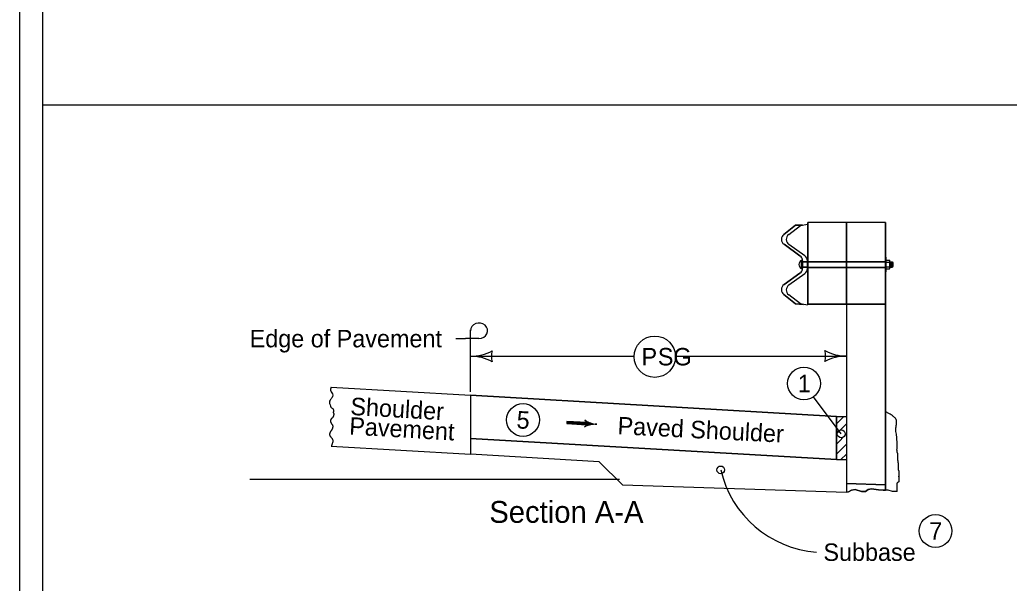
# Model space of a CAD drawing. Extents: x 6410 to 81668, y 3928 to 11667.
# Drawn here: x 10133 to 11038, y 8912 to 9428 of the extents above; entities that cross this region are included whole.
import ezdxf

# ---------------------------------------------------------------- set-up
doc = ezdxf.new("R2010")
doc.units = 0
for name, color, linetype in [('dsnCellElements', 7, 'Continuous'), ('dsnNonPlotable', 7, 'Continuous'), ('dsnShtPlotShapeBatchPrint', 7, 'Continuous'), ('dsnStdBlockModified', 7, 'Continuous'), ('Level 11', 7, 'Continuous'), ('Level 14', 7, 'Continuous'), ('Level 3', 7, 'Continuous'), ('Level 7', 7, 'Continuous'), ('Level 8', 7, 'Continuous')]:
    doc.layers.add(name, color=color, linetype=linetype)

msp = doc.modelspace()

# ---------------------------------------------------------------- linework, layer by layer
at = {"layer": 'dsnCellElements'}
for p, q in [((10545.11, 9123.38), (10545.11, 9144.24)), ((10531.74, 9136.23), (10540.43, 9136.23)), ((10552.92, 9136.23), (10540.43, 9136.23)), ((10545.11, 9087.45), (10545.11, 9123.38)), ((10651.5, 9058.34), (10633.29, 9059.39)), ((10651.51, 9059.35), (10651.51, 9059.35)), ((10651.39, 9057.4), (10651.39, 9057.4))]:
    msp.add_line(p, q, dxfattribs=at)
for points in [[(10651.52, 9059.29), (10633.36, 9060.33), (10633.23, 9058.45), (10651.39, 9057.4), (10651.45, 9059.02), (10633.58, 9060.11), (10633.52, 9058.61), (10651.01, 9057.67), (10651.13, 9058.79), (10633.81, 9059.85), (10633.79, 9058.85), (10650.8, 9057.87), (10650.89, 9058.57), (10634, 9059.63), (10633.98, 9059.07), (10650.59, 9058.13)], [(10651.12, 9060.54), (10651.81, 9059.37), (10651.79, 9057.73), (10651.03, 9056.33), (10653.79, 9057.19), (10656.98, 9057.84), (10657.88, 9057.98), (10655.64, 9058.53), (10652.41, 9059.76), (10651.47, 9060.29), (10651.59, 9056.78), (10656.54, 9057.99), (10651.9, 9059.58), (10651.91, 9057.16), (10655.31, 9058.09), (10652.31, 9058.95), (10652.08, 9057.56), (10654.24, 9058.06), (10652.65, 9058.57), (10652.51, 9057.91), (10653.3, 9058.08)]]:
    msp.add_lwpolyline(points, dxfattribs=at)
for centre, major_axis, start_param, end_param in [((10552.92, 9143.37), (-7.81, 0), 1.570796, 6.283185), ((10647.73, 9058.56), (3.88, 0), 5.202895, 7.237436), ((10662.79, 9077.98), (-22.17, 0), 0.954258, 1.478381), ((10660, 9037.56), (22.17, 0), 1.537172, 2.061295)]:
    msp.add_ellipse(centre, major_axis=major_axis, ratio=0.913811, start_param=start_param, end_param=end_param, dxfattribs=at)
at = {"layer": 'dsnNonPlotable'}
msp.add_line((10153.18, 9917.9), (10153.18, 8307.9), dxfattribs=at)
at = {"layer": 'dsnShtPlotShapeBatchPrint'}
for p, q in [((10545.11, 9120.06), (10694.94, 9120.06)), ((10732.8, 9120.22), (10889.5, 9120.22))]:
    msp.add_line(p, q, dxfattribs=at)
msp.add_circle((10713.87, 9119.66), 18.93, dxfattribs=at)
for centre, radius, start, end in [((10545.11, 9162.56), 42.5, 270, 298.07249), ((10580.75, 9120.06), 16.42, 162.26665, 197.73335), ((10853.87, 9120.22), 16.42, 342.26665, 17.73335), ((10889.5, 9162.72), 42.5, 241.92751, 270), ((10545.11, 9077.56), 42.5, 61.92751, 90), ((10889.5, 9077.72), 42.5, 90, 118.07249), ((10869.48, 9038.15), 97.76, 193.07698, 265.55799)]:
    msp.add_arc(centre, radius, start, end, dxfattribs=at)
at = {"layer": 'dsnStdBlockModified'}
for p, q in [((10832.02, 9231.67), (10842.78, 9240.07)), ((10836.45, 9231.44), (10847.23, 9239.85)), ((10842.78, 9240.07), (10849.11, 9240.18)), ((10847.23, 9239.85), (10853.56, 9240.97)), ((10925.05, 9242.43), (10853.96, 9242.43)), ((10853.96, 9167.78), (10853.96, 9242.43)), ((10889.5, 9167.78), (10889.5, 9242.43)), ((10925.05, 9242.43), (10925.05, 8997.39)), ((10846.72, 9212.14), (10832.21, 9222.55)), ((10851.19, 9211.9), (10836.63, 9222.35)), ((10848.34, 9200.03), (10848.34, 9208.11)), ((10848.34, 9206.42), (10853.77, 9206.42)), ((10849.12, 9200.69), (10849.11, 9207.5)), ((10849.11, 9200.69), (10849.12, 9204.1)), ((10849.12, 9204.1), (10849.12, 9200.69)), ((10849.29, 9206.42), (10853.96, 9206.42)), ((10853.56, 9203.88), (10853.56, 9207.29)), ((10853.56, 9200.47), (10853.56, 9203.88)), ((10853.56, 9203.88), (10853.56, 9200.47)), ((10853.96, 9206.76), (10925.05, 9206.76)), ((10853.96, 9206.42), (10925.05, 9206.42)), ((10925.05, 9210.73), (10925.73, 9210.73)), ((10925.73, 9197.4), (10925.73, 9210.73)), ((10925.73, 9208.1), (10928.7, 9208.1)), ((10925.73, 9206.08), (10928.7, 9206.08)), ((10929.06, 9201.03), (10929.06, 9207.09)), ((10929.06, 9206.39), (10931.43, 9206.39)), ((10929.95, 9206.39), (10929.95, 9201.73)), ((10930.69, 9206.39), (10930.69, 9201.73)), ((10931.43, 9206.39), (10931.88, 9205.86)), ((10931.43, 9206.39), (10931.43, 9201.73)), ((10931.88, 9205.86), (10931.88, 9202.26)), ((10832.21, 9185.65), (10846.72, 9196.06)), ((10836.63, 9185.41), (10851.19, 9195.86)), ((10848.34, 9201.76), (10853.96, 9201.76)), ((10853.95, 9201.42), (10925.05, 9201.42)), ((10853.96, 9201.76), (10925.05, 9201.76)), ((10925.05, 9197.4), (10925.73, 9197.4)), ((10925.73, 9202.04), (10928.7, 9202.04)), ((10925.73, 9200.02), (10928.7, 9200.02)), ((10929.06, 9201.73), (10931.43, 9201.73)), ((10931.88, 9202.26), (10931.43, 9201.73)), ((10842.78, 9168.13), (10832.02, 9176.52)), ((10847.23, 9167.91), (10836.45, 9176.32)), ((10849.88, 9167.44), (10842.78, 9168.13)), ((10853.56, 9166.79), (10847.23, 9167.91)), ((10889.5, 9167.78), (10853.96, 9167.78)), ((10889.5, 9167.78), (10889.5, 8995.55)), ((10417.65, 9091.72), (10545.11, 9084.31)), ((10545.11, 9084.31), (10545.11, 9030.29)), ((10545.11, 9084.31), (10880.25, 9064.82)), ((10880.25, 9064.82), (10545.11, 9084.31)), ((10545.11, 9084.31), (10545.11, 9044.71)), ((10880.25, 9058.07), (10886.99, 9064.82)), ((10880.25, 9058.07), (10886.99, 9064.82)), ((10880.25, 9058.07), (10886.99, 9064.82)), ((10880.25, 9058.07), (10886.99, 9064.82)), ((10880.25, 9064.82), (10889.49, 9064.82)), ((10880.25, 9064.82), (10880.25, 9025.39)), ((10880.25, 9025.39), (10880.25, 9064.82)), ((10880.25, 9048.89), (10889.49, 9058.12)), ((10880.25, 9048.89), (10889.49, 9058.12)), ((10880.25, 9048.89), (10889.49, 9058.12)), ((10880.25, 9048.89), (10889.49, 9058.12)), ((10935.1, 9058.05), (10935.1, 9058.05)), ((10880.25, 9025.39), (10545.11, 9044.71)), ((10545.11, 9044.71), (10880.25, 9025.39)), ((10880.25, 9039.66), (10889.49, 9048.9)), ((10880.25, 9039.66), (10889.49, 9048.9)), ((10880.25, 9039.66), (10889.49, 9048.9)), ((10880.25, 9039.66), (10889.49, 9048.9)), ((10417.68, 9037.7), (10545.11, 9030.29)), ((10880.25, 9030.43), (10889.49, 9039.67)), ((10662.95, 9023.5), (10545.11, 9030.29)), ((10662.95, 9023.5), (10684.29, 9002.28)), ((10880.25, 9025.39), (10889.49, 9025.39)), ((10884.35, 9025.39), (10889.49, 9030.53)), ((10343.06, 9007.46), (10681.56, 9007.46)), ((10684.29, 9002.28), (10889.5, 8995.55))]:
    msp.add_line(p, q, dxfattribs=at)
for points in [[(10929.05, 9201.36), (10929, 9201.62), (10928.96, 9201.8), (10928.87, 9201.95), (10928.75, 9202.04), (10928.83, 9202.14), (10928.91, 9202.36), (10928.97, 9202.68), (10929.05, 9203.43), (10929.05, 9201.35), (10929.03, 9201.49), (10928.99, 9201.71), (10928.91, 9201.92), (10928.79, 9202.03), (10928.83, 9202.12), (10928.89, 9202.27), (10928.99, 9202.77), (10929.03, 9203.15), (10929.03, 9201.54), (10929, 9201.66), (10928.96, 9201.83), (10928.83, 9202.03), (10928.88, 9202.2), (10928.96, 9202.54), (10929.02, 9202.86), (10929.01, 9201.7), (10928.97, 9201.83), (10928.86, 9202.02), (10928.9, 9202.24), (10928.96, 9202.5), (10928.99, 9202.67), (10928.99, 9201.8), (10928.93, 9201.91), (10928.88, 9202.03), (10928.97, 9202.48), (10928.97, 9201.88), (10928.9, 9202.02), (10928.95, 9202.31), (10928.95, 9201.96), (10928.92, 9202.03), (10928.93, 9202.13), (10928.93, 9202.06)], [(10928.76, 9206.09), (10928.83, 9206.13), (10928.91, 9206.23), (10928.99, 9206.45), (10929.05, 9206.74), (10929.05, 9204.79), (10928.99, 9205.3), (10928.94, 9205.67), (10928.82, 9206), (10928.76, 9206.08), (10928.82, 9206.09), (10928.92, 9206.24), (10929.01, 9206.46), (10929.03, 9206.62), (10929.03, 9205.08), (10928.96, 9205.57), (10928.9, 9205.84), (10928.8, 9206.06), (10928.83, 9206.07), (10928.97, 9206.29), (10929.01, 9206.44), (10929.01, 9205.34), (10928.82, 9206.05), (10928.99, 9206.33), (10928.99, 9205.48), (10928.85, 9206.04), (10928.97, 9206.26), (10928.98, 9205.62), (10928.87, 9206.02), (10928.96, 9206.2), (10928.96, 9205.78), (10928.89, 9206.01), (10928.94, 9206.12), (10928.94, 9205.92), (10928.91, 9205.99), (10928.92, 9206.04)], [(10935.57, 9034.21), (10935.51, 9033.94), (10935.51, 9033.74), (10935.51, 9033.55), (10935.51, 9033.35), (10935.51, 9033.15), (10935.51, 9032.96), (10935.51, 9032.67), (10935.51, 9032.47), (10935.61, 9032.18), (10935.71, 9031.88), (10935.9, 9031.69), (10935.9, 9031.49), (10936, 9031.3), (10936, 9031.1), (10936, 9030.91), (10936.1, 9030.81), (10936.1, 9030.61), (10936.1, 9030.42), (10936.1, 9030.22), (10936.1, 9030.03), (10936.1, 9029.83), (10936.1, 9029.54), (10936.1, 9029.25), (10936.1, 9029.05), (10936.1, 9028.76), (10936.1, 9028.56), (10936.1, 9028.37), (10936.2, 9028.27), (10936.2, 9028.07), (10936.2, 9027.88), (10936.2, 9027.68), (10936.2, 9027.49), (10936.2, 9027.29), (10936.2, 9027.1), (10936.2, 9026.9), (10936.2, 9026.71), (10936.2, 9026.51), (10936.2, 9026.32), (10936.2, 9026.12), (10936.2, 9025.92), (10936.2, 9025.73), (10936.2, 9025.53), (10936.2, 9025.34), (10936.2, 9025.14), (10936.2, 9024.95), (10936.2, 9024.75), (10936.29, 9024.65), (10936.29, 9024.46), (10936.29, 9024.26), (10936.39, 9024.17), (10936.39, 9023.97), (10936.39, 9023.77), (10936.49, 9023.68), (10936.49, 9023.48), (10936.49, 9023.29), (10936.49, 9023.09), (10936.49, 9022.8), (10936.59, 9022.5), (10936.59, 9022.31), (10936.59, 9022.11), (10936.59, 9021.92), (10936.59, 9021.72), (10936.59, 9021.53), (10936.59, 9021.33), (10936.59, 9021.14), (10936.59, 9020.94), (10936.59, 9020.75), (10936.59, 9020.55), (10936.59, 9020.36), (10936.59, 9020.16), (10936.59, 9019.96), (10936.59, 9019.77), (10936.59, 9019.57), (10936.59, 9019.38), (10936.59, 9019.18), (10936.59, 9018.99), (10936.59, 9018.79), (10936.59, 9018.6), (10936.59, 9018.4), (10936.59, 9018.21), (10936.59, 9018.01), (10936.59, 9017.81), (10936.59, 9017.62), (10936.59, 9017.42), (10936.59, 9017.23), (10936.59, 9017.03), (10936.59, 9016.84), (10936.68, 9016.74), (10936.68, 9016.45), (10936.68, 9016.25), (10936.78, 9016.06), (10936.88, 9015.76), (10936.88, 9015.57), (10936.98, 9015.47), (10936.98, 9015.27), (10937.07, 9015.18), (10937.17, 9015.08), (10937.17, 9014.88), (10937.17, 9014.69), (10937.17, 9014.49), (10937.27, 9014.4), (10937.27, 9014.2), (10937.27, 9014), (10937.27, 9013.81), (10937.27, 9013.61), (10937.27, 9013.42), (10937.27, 9013.22), (10937.27, 9013.03), (10937.27, 9012.83), (10937.27, 9012.64), (10937.27, 9012.44), (10937.27, 9012.25), (10937.27, 9012.05), (10937.27, 9011.85), (10937.27, 9011.66), (10937.27, 9011.46), (10937.27, 9011.27), (10937.27, 9011.07), (10937.27, 9010.88), (10937.27, 9010.68), (10937.27, 9010.49), (10937.27, 9010.29), (10937.27, 9010.1), (10937.27, 9009.9), (10937.27, 9009.71), (10937.27, 9009.51), (10937.27, 9009.51), (10937.27, 9009.8), (10937.27, 9010), (10937.27, 9010.19), (10937.27, 9010), (10937.27, 9009.8), (10937.27, 9009.61), (10937.27, 9009.41), (10937.27, 9009.22), (10937.27, 9009.02), (10937.27, 9008.83), (10937.27, 9008.63), (10937.27, 9008.44), (10937.27, 9008.24), (10937.27, 9008.04), (10937.27, 9007.85), (10937.27, 9007.65), (10937.27, 9007.46), (10937.27, 9007.26), (10937.17, 9007.16), (10937.17, 9006.97), (10937.17, 9006.77), (10937.17, 9006.58), (10937.17, 9006.38), (10937.17, 9006.19), (10937.17, 9005.99), (10937.17, 9005.8), (10937.17, 9005.6), (10937.17, 9005.41), (10937.17, 9005.21), (10937.07, 9005.11), (10936.98, 9004.92), (10936.88, 9004.82), (10936.78, 9004.72), (10936.68, 9004.62), (10936.49, 9004.53), (10936.29, 9004.53), (10936.2, 9004.43), (10936.1, 9004.33), (10936, 9004.23), (10935.8, 9004.14), (10935.71, 9004.04), (10935.71, 9003.84), (10935.61, 9003.75), (10935.61, 9003.55), (10935.61, 9003.35), (10935.61, 9003.16), (10935.61, 8996.34)], [(10935.74, 8996.34), (10931.59, 8996.22), (10927.46, 8997.39), (10922.9, 8997.39), (10918.66, 8997.81), (10912.41, 8998.56), (10909.33, 8997.92), (10906.68, 8996.12), (10902.97, 8996.33), (10897.36, 8997.92), (10894.07, 8997.39), (10891.31, 8995.8), (10889.5, 8995.55)]]:
    msp.add_lwpolyline(points, dxfattribs=at)
msp.add_circle((10593.23, 9061.73), 15, dxfattribs=at)
for centre, radius, start, end in [((10835.49, 9227.18), 5.68, 127.75002, 234.69086), ((10839.94, 9226.96), 5.68, 127.75002, 234.69086), ((10850.42, 9204.08), 4.54, 117.20289, 242.8461), ((10843.44, 9207.5), 5.68, 360, 54.69099), ((10847.88, 9207.28), 5.68, 360, 54.69099), ((10843.44, 9200.69), 5.68, 305.30901, 0), ((10847.88, 9200.47), 5.68, 305.30901, 0), ((10835.49, 9181.01), 5.68, 125.30914, 232.24998), ((10839.94, 9180.79), 5.68, 125.30914, 232.24998)]:
    msp.add_arc(centre, radius, start, end, dxfattribs=at)
for centre in [(10928.7, 9207.09), (10928.7, 9201.03)]:
    msp.add_ellipse(centre, major_axis=(0, -1.01), ratio=0.362258, start_param=6.283156, end_param=9.424748, dxfattribs=at)
for points in [[(10417.65, 9091.72), (10417.15, 9088.11), (10418.19, 9086.61), (10419.05, 9084.31), (10418.45, 9082.25), (10416.54, 9079.88), (10416.02, 9077.98), (10416.54, 9075.68), (10417.41, 9073.3), (10418.45, 9072.59), (10419.83, 9070.06), (10419.82, 9069.22)], [(10417.86, 9052.11), (10418.07, 9052.35), (10418.27, 9052.61), (10418.62, 9053.17), (10418.9, 9053.76), (10419.02, 9054.07), (10419.12, 9054.39), (10419.25, 9055.01), (10419.3, 9055.63), (10419.25, 9056.21), (10419.19, 9056.49), (10419.16, 9056.63), (10419.11, 9056.76), (10418.9, 9057.13), (10418.62, 9057.49), (10418.32, 9057.86), (10418.07, 9058.26), (10417.93, 9058.54), (10417.79, 9058.83), (10417.53, 9059.4), (10417.33, 9059.97), (10417.26, 9060.26), (10417.2, 9060.56), (10417.19, 9060.68), (10417.19, 9060.81), (10417.34, 9061.59), (10417.55, 9062.11), (10417.81, 9062.62), (10418.25, 9063.25), (10418.77, 9063.8), (10419.29, 9064.35), (10419.52, 9064.65), (10419.72, 9064.99), (10419.92, 9065.46), (10420.08, 9065.94), (10420.18, 9066.42), (10420.22, 9066.65), (10420.23, 9066.77), (10420.24, 9066.89), (10420.19, 9067.4), (10420.04, 9067.92), (10419.99, 9068.04), (10419.93, 9068.17), (10419.88, 9068.3), (10419.86, 9068.43), (10419.82, 9069.22)], [(10935.57, 9034.21), (10935.89, 9037.11), (10935.67, 9041.98), (10935.23, 9047.73), (10934.56, 9052.15), (10934.78, 9055.47), (10935.23, 9059.67), (10934.56, 9062.76), (10932.35, 9064.75), (10930.36, 9066.52), (10928.15, 9067.63), (10925.94, 9068.96), (10925.06, 9069.62)], [(10417.86, 9052.11), (10417.64, 9051.87), (10417.4, 9051.64), (10417.16, 9051.39), (10416.98, 9051.13), (10416.84, 9050.84), (10416.7, 9050.56), (10416.44, 9049.98), (10416.33, 9049.7), (10416.23, 9049.41), (10416.16, 9049.12), (10416.13, 9048.98), (10416.11, 9048.83), (10416.12, 9048.31), (10416.25, 9047.8), (10416.46, 9047.28), (10416.72, 9046.77), (10417.16, 9046.13), (10417.68, 9045.59), (10418.2, 9045.04), (10418.43, 9044.73), (10418.63, 9044.39), (10419.03, 9043.45), (10419.14, 9042.97), (10419.15, 9042.49), (10419.11, 9042.2), (10419.06, 9041.92), (10419.01, 9041.63), (10418.94, 9041.35), (10418.63, 9040.2), (10418.45, 9039.59), (10418.25, 9038.99), (10418.03, 9038.4), (10417.9, 9038.11), (10417.76, 9037.82), (10417.68, 9037.7)]]:
    msp.add_spline(points, degree=3, dxfattribs=at)
at = {"layer": 'Level 11'}
for p, q in [((12308.76, 9349.9), (10153.18, 9349.9)), ((10884.57, 9048.99), (10859.18, 9082.92))]:
    msp.add_line(p, q, dxfattribs=at)
at = {"layer": 'Level 14'}
msp.add_circle((10774.25, 9016.03), 3.54, dxfattribs=at)
at = {"layer": 'Level 3'}
for p, q in [((10832.21, 9222.55), (10846.72, 9212.14)), ((10846.72, 9196.06), (10832.21, 9185.65))]:
    msp.add_line(p, q, dxfattribs=at)
for points in [[(10836.46, 9231.45), (10836.45, 9231.44), (10847.23, 9239.85), (10849.11, 9240.18), (10842.78, 9240.07), (10832.02, 9231.67)], [(10889.5, 9206.76), (10889.5, 9242.43), (10853.96, 9242.43), (10853.96, 9206.76), (10853.96, 9206.76), (10889.5, 9206.76)], [(10925.05, 9206.76), (10925.05, 9210.76), (10925.05, 9242.43), (10889.5, 9242.43), (10889.5, 9206.76), (10925.05, 9206.76)], [(10851.17, 9211.92), (10851.19, 9211.9), (10836.63, 9222.35), (10836.66, 9222.33)], [(10849.11, 9207.5), (10849.11, 9206.42), (10853.56, 9206.42), (10853.56, 9207.29), (10853.56, 9207.28)], [(10853.96, 9206.42), (10853.96, 9201.76), (10853.96, 9201.76), (10889.5, 9201.76), (10889.5, 9206.42), (10853.96, 9206.42), (10853.96, 9206.42)], [(10925.05, 9201.76), (10925.05, 9206.42), (10889.5, 9206.42), (10889.5, 9201.76), (10925.05, 9201.76)], [(10836.66, 9185.43), (10836.63, 9185.41), (10851.19, 9195.86), (10851.17, 9195.84)], [(10853.56, 9200.47), (10853.56, 9200.47), (10853.56, 9201.76), (10849.12, 9201.76), (10849.12, 9200.69), (10849.12, 9201.76), (10849.11, 9201.76), (10849.11, 9200.69)], [(10853.96, 9201.42), (10853.96, 9167.78), (10889.5, 9167.78), (10889.5, 9201.42), (10853.96, 9201.42)], [(10925.05, 9167.78), (10925.05, 9197.42), (10925.05, 9201.42), (10889.5, 9201.42), (10889.5, 9167.78), (10925.05, 9167.78)], [(10832.02, 9176.52), (10842.78, 9168.13), (10849.88, 9167.44), (10847.23, 9167.91), (10836.45, 9176.32), (10836.46, 9176.31)], [(10925.05, 9002.44), (10925.05, 9167.78), (10889.5, 9167.78), (10889.5, 9064.82), (10889.5, 9058.12), (10889.5, 9058.12), (10889.5, 9058.12), (10889.5, 9048.9), (10889.5, 9048.9), (10889.5, 9048.9), (10889.5, 9039.75), (10889.5, 9039.75), (10889.5, 9039.75), (10889.5, 9032.82), (10889.5, 9003.6), (10925.05, 9002.44)], [(10925.05, 9002.44), (10889.5, 9003.6), (10889.5, 8995.55), (10891.31, 8995.8), (10894.07, 8997.39), (10897.36, 8997.92), (10902.97, 8996.33), (10906.68, 8996.12), (10909.33, 8997.92), (10912.41, 8998.56), (10918.66, 8997.81), (10922.9, 8997.39), (10925.05, 8997.39), (10925.05, 9002.44)]]:
    msp.add_lwpolyline(points, dxfattribs=at)
msp.add_lwpolyline([(10853.56, 9206.42), (10849.11, 9206.42), (10849.12, 9202.96), (10849.12, 9204.1), (10849.12, 9201.76), (10853.56, 9201.76)], close=True, dxfattribs=at)
for centre, start, end in [((10835.49, 9227.18), 127.75002, 234.69086), ((10839.94, 9226.96), 127.75002, 234.69086), ((10843.44, 9207.5), 0, 54.69099), ((10847.88, 9207.28), 0, 54.69099), ((10843.44, 9200.69), 305.30901, 0), ((10847.88, 9200.47), 305.30901, 0), ((10835.49, 9181.01), 125.30914, 232.24998), ((10839.94, 9180.79), 125.30914, 232.24998)]:
    msp.add_arc(centre, 5.68, start, end, dxfattribs=at)
at = {"layer": 'Level 7'}
for centre, radius in [((10850.44, 9095.11), 15), ((10593.23, 9061.73), 15), ((10884.57, 9048.99), 3.58), ((10970.88, 8960.06), 15)]:
    msp.add_circle(centre, radius, dxfattribs=at)
at = {"layer": 'Level 8'}
msp.add_lwpolyline([(10132.52, 9944.02), (13267.53, 9944.02), (13267.53, 7924.02), (10132.52, 7924.02)], close=True, dxfattribs=at)

# ---------------------------------------------------------------- texts
at = {"layer": 'dsnCellElements'}
for s, height, p in [('Edge of Pavement', 16, (10342.98, 9128.23)), ('Section A-A', 20, (10562.37, 8967.53)), ('Subbase', 16, (10868.26, 8932.68))]:
    msp.add_text(s, height=height, dxfattribs=at).set_placement(p)
for s, rotation, p in [('Shoulder', 356.73462, (10434.87, 9066.38)), ('Pavement', 356.73462, (10433.84, 9048.41)), ('Paved Shoulder ', 357.0678, (10679.51, 9048.71))]:
    msp.add_text(s, height=16, rotation=rotation, dxfattribs=at).set_placement(p)
at = {"layer": 'dsnShtPlotShapeBatchPrint'}
for s, p in [('P', (10701.74, 9111.66)), ('SG', (10716.66, 9111.66))]:
    msp.add_text(s, height=16, dxfattribs=at).set_placement(p)
at = {"layer": 'Level 7'}
for s, p in [('1', (10844.82, 9087.11)), ('7', (10965.18, 8952.06))]:
    msp.add_text(s, height=16, dxfattribs=at).set_placement(p)
msp.add_text('5', height=16, rotation=356.69973, dxfattribs=at).set_placement((10587.01, 9054.08))

doc.saveas('drawing.dxf')
